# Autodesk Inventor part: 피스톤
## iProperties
Manager: KYOUNG IL JANG
Company: 한국ATC센터
Created: 2012-10
Part Number: 피스톤
Document SubType Name: Modeling
Density: 1 g/cm^3
Checked By: KYOUNG IL JANG
Vendor: CBT Solutions
Designer: KYOUNG IL JANG
Author: KYOUNG IL JANG
